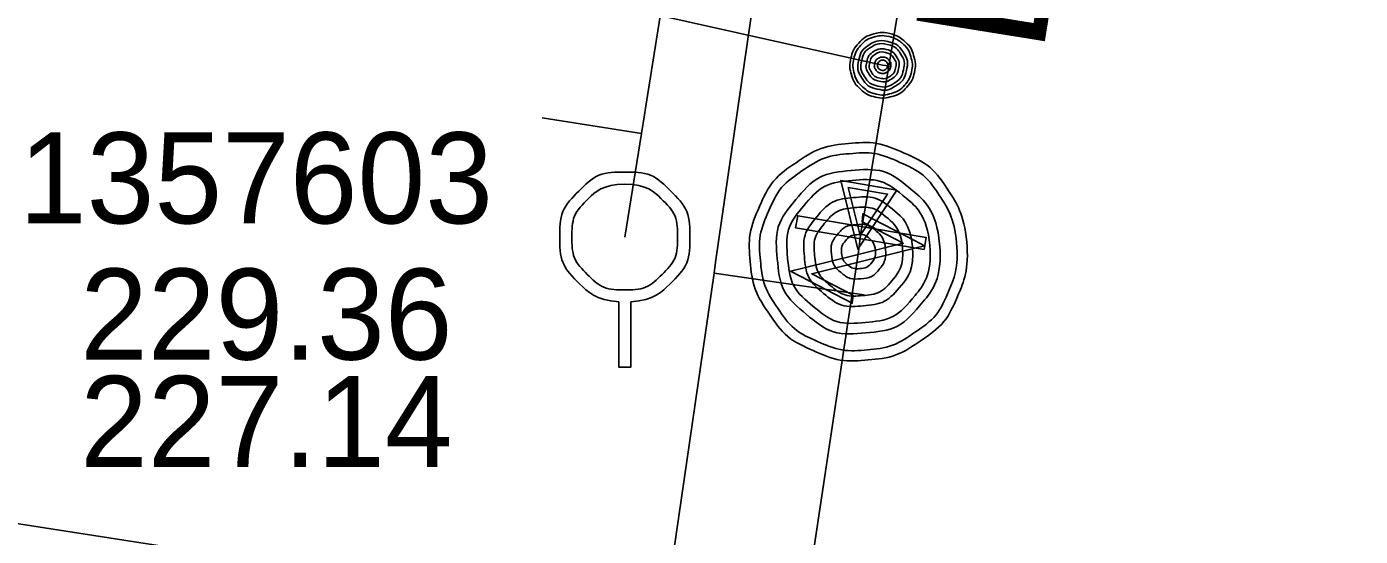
# Model space of a CAD drawing. Extents: x -595129 to -593591, y -1168385 to -1166898.
# Drawn here: x -594572.5 to -594551.99, y -1167292.77 to -1167284.93 of the extents above; entities that cross this region are included whole.
import ezdxf

# ---------------------------------------------------------------- set-up
doc = ezdxf.new("R2010")
doc.units = 0
for name, color, linetype in [('DA V Řad popis', 7, 'Continuous'), ('Default', 7, 'Continuous'), ('Identifikace', 7, 'Continuous'), ('Kanalizační přípojka', 7, 'Continuous'), ('Kanalizační stoka', 7, 'Continuous'), ('Kanalizační šachta', 7, 'Continuous'), ('Popis šachty', 7, 'Continuous'), ('V Lomový bod', 7, 'Continuous'), ('V Přípojka', 7, 'Continuous'), ('V Uzávěr', 7, 'Continuous'), ('V Řad', 7, 'Continuous')]:
    doc.layers.add(name, color=color, linetype=linetype)

msp = doc.modelspace()

# ---------------------------------------------------------------- linework, layer by layer
at = {"layer": 'Default'}
for points in [[(-594559.227, -1167285.037), (-594559.104, -1167285.065), (-594559.001, -1167285.154), (-594558.898, -1167285.243), (-594558.859, -1167285.375), (-594558.819, -1167285.507), (-594558.848, -1167285.635), (-594558.876, -1167285.762), (-594558.966, -1167285.864), (-594559.057, -1167285.966), (-594559.188, -1167286.004), (-594559.318, -1167286.042), (-594559.446, -1167286.014), (-594559.572, -1167285.986), (-594559.674, -1167285.895), (-594559.776, -1167285.805), (-594559.814, -1167285.674), (-594559.853, -1167285.544), (-594559.824, -1167285.417), (-594559.796, -1167285.289), (-594559.704, -1167285.186), (-594559.612, -1167285.083), (-594559.481, -1167285.046), (-594559.351, -1167285.009), (-594559.227, -1167285.037)], [(-594559.237, -1167285.083), (-594559.349, -1167285.058), (-594559.468, -1167285.091), (-594559.586, -1167285.124), (-594559.669, -1167285.218), (-594559.753, -1167285.311), (-594559.779, -1167285.427), (-594559.804, -1167285.542), (-594559.77, -1167285.66), (-594559.735, -1167285.778), (-594559.642, -1167285.86), (-594559.55, -1167285.942), (-594559.435, -1167285.968), (-594559.32, -1167285.994), (-594559.201, -1167285.959), (-594559.083, -1167285.924), (-594559.001, -1167285.832), (-594558.919, -1167285.74), (-594558.893, -1167285.625), (-594558.867, -1167285.509), (-594558.904, -1167285.389), (-594558.94, -1167285.269), (-594559.033, -1167285.188), (-594559.126, -1167285.108), (-594559.237, -1167285.083)], [(-594559.255, -1167285.159), (-594559.101, -1167285.193), (-594559.018, -1167285.325), (-594558.936, -1167285.456), (-594558.97, -1167285.608), (-594559.004, -1167285.76), (-594559.135, -1167285.843), (-594559.266, -1167285.926), (-594559.419, -1167285.892), (-594559.57, -1167285.858), (-594559.653, -1167285.727), (-594559.736, -1167285.596), (-594559.702, -1167285.444), (-594559.668, -1167285.292), (-594559.538, -1167285.208), (-594559.407, -1167285.125), (-594559.255, -1167285.159)], [(-594559.265, -1167285.204), (-594559.398, -1167285.174), (-594559.513, -1167285.247), (-594559.627, -1167285.32), (-594559.657, -1167285.453), (-594559.687, -1167285.586), (-594559.614, -1167285.7), (-594559.542, -1167285.815), (-594559.408, -1167285.845), (-594559.275, -1167285.875), (-594559.161, -1167285.802), (-594559.046, -1167285.729), (-594559.016, -1167285.596), (-594558.986, -1167285.463), (-594559.059, -1167285.348), (-594559.131, -1167285.234), (-594559.265, -1167285.204)], [(-594559.282, -1167285.281), (-594559.179, -1167285.304), (-594559.124, -1167285.392), (-594559.069, -1167285.479), (-594559.092, -1167285.581), (-594559.114, -1167285.682), (-594559.202, -1167285.737), (-594559.289, -1167285.792), (-594559.391, -1167285.77), (-594559.492, -1167285.747), (-594559.547, -1167285.66), (-594559.603, -1167285.572), (-594559.58, -1167285.471), (-594559.557, -1167285.37), (-594559.471, -1167285.314), (-594559.384, -1167285.258), (-594559.282, -1167285.281)], [(-594559.292, -1167285.327), (-594559.374, -1167285.308), (-594559.445, -1167285.353), (-594559.516, -1167285.398), (-594559.535, -1167285.481), (-594559.553, -1167285.563), (-594559.508, -1167285.634), (-594559.463, -1167285.705), (-594559.381, -1167285.723), (-594559.299, -1167285.742), (-594559.227, -1167285.697), (-594559.156, -1167285.652), (-594559.138, -1167285.569), (-594559.119, -1167285.487), (-594559.164, -1167285.416), (-594559.209, -1167285.345), (-594559.292, -1167285.327)], [(-594559.309, -1167285.403), (-594559.258, -1167285.415), (-594559.23, -1167285.459), (-594559.202, -1167285.502), (-594559.214, -1167285.553), (-594559.225, -1167285.603), (-594559.269, -1167285.631), (-594559.313, -1167285.659), (-594559.364, -1167285.648), (-594559.414, -1167285.636), (-594559.442, -1167285.593), (-594559.469, -1167285.549), (-594559.458, -1167285.498), (-594559.447, -1167285.448), (-594559.403, -1167285.42), (-594559.36, -1167285.392), (-594559.309, -1167285.403)], [(-594559.319, -1167285.449), (-594559.351, -1167285.442), (-594559.378, -1167285.459), (-594559.405, -1167285.476), (-594559.413, -1167285.508), (-594559.42, -1167285.54), (-594559.402, -1167285.567), (-594559.385, -1167285.595), (-594559.353, -1167285.602), (-594559.321, -1167285.609), (-594559.294, -1167285.591), (-594559.267, -1167285.574), (-594559.26, -1167285.542), (-594559.253, -1167285.51), (-594559.27, -1167285.483), (-594559.287, -1167285.456), (-594559.319, -1167285.449)], [(-594558.042, -1167288.241), (-594558.004, -1167288.661), (-594558.183, -1167289.079), (-594558.361, -1167289.496), (-594558.741, -1167289.758), (-594559.122, -1167290.02), (-594559.557, -1167290.059), (-594559.99, -1167290.098), (-594560.406, -1167289.915), (-594560.821, -1167289.731), (-594561.077, -1167289.355), (-594561.332, -1167288.978), (-594561.372, -1167288.544), (-594561.411, -1167288.113), (-594561.228, -1167287.696), (-594561.044, -1167287.28), (-594560.668, -1167287.024), (-594560.292, -1167286.769), (-594559.86, -1167286.73), (-594559.424, -1167286.69), (-594559.003, -1167286.877), (-594558.582, -1167287.064), (-594558.331, -1167287.442), (-594558.081, -1167287.82), (-594558.042, -1167288.241)], [(-594558.198, -1167288.255), (-594558.233, -1167287.875), (-594558.46, -1167287.532), (-594558.687, -1167287.189), (-594559.069, -1167287.019), (-594559.451, -1167286.85), (-594559.846, -1167286.886), (-594560.237, -1167286.921), (-594560.578, -1167287.152), (-594560.918, -1167287.383), (-594561.085, -1167287.761), (-594561.251, -1167288.139), (-594561.216, -1167288.53), (-594561.18, -1167288.923), (-594560.948, -1167289.265), (-594560.716, -1167289.607), (-594560.34, -1167289.773), (-594559.963, -1167289.939), (-594559.571, -1167289.903), (-594559.176, -1167289.867), (-594558.832, -1167289.629), (-594558.487, -1167289.391), (-594558.325, -1167289.014), (-594558.164, -1167288.636), (-594558.198, -1167288.255)], [(-594563.394, -1167289.166), (-594563.747, -1167289.137), (-594564.007, -1167288.877), (-594564.3, -1167288.586), (-594564.3, -1167288.172), (-594564.3, -1167287.756), (-594564.01, -1167287.463), (-594563.72, -1167287.17), (-594563.302, -1167287.17), (-594562.882, -1167287.17), (-594562.591, -1167287.463), (-594562.3, -1167287.756), (-594562.3, -1167288.172), (-594562.3, -1167288.586), (-594562.593, -1167288.877), (-594562.851, -1167289.137), (-594563.206, -1167289.166)], [(-594558.459, -1167288.277), (-594558.411, -1167288.803), (-594558.744, -1167289.199), (-594559.077, -1167289.596), (-594559.595, -1167289.643), (-594560.112, -1167289.69), (-594560.51, -1167289.357), (-594560.909, -1167289.025), (-594560.956, -1167288.504), (-594561.003, -1167287.991), (-594560.671, -1167287.592), (-594560.339, -1167287.193), (-594559.822, -1167287.146), (-594559.303, -1167287.099), (-594558.905, -1167287.428), (-594558.506, -1167287.757), (-594558.459, -1167288.277)], [(-594563.302, -1167287.356), (-594563.64, -1167287.356), (-594563.877, -1167287.593), (-594564.114, -1167287.83), (-594564.114, -1167288.168), (-594564.114, -1167288.506), (-594563.877, -1167288.743), (-594563.64, -1167288.981), (-594563.302, -1167288.981), (-594562.964, -1167288.981), (-594562.727, -1167288.743), (-594562.489, -1167288.506), (-594562.489, -1167288.168), (-594562.489, -1167287.83), (-594562.726, -1167287.593), (-594562.962, -1167287.356), (-594563.302, -1167287.356)], [(-594558.611, -1167288.291), (-594558.653, -1167287.836), (-594559.001, -1167287.547), (-594559.35, -1167287.257), (-594559.803, -1167287.298), (-594560.257, -1167287.339), (-594560.547, -1167287.687), (-594560.838, -1167288.035), (-594560.797, -1167288.49), (-594560.755, -1167288.944), (-594560.407, -1167289.234), (-594560.058, -1167289.524), (-594559.605, -1167289.483), (-594559.151, -1167289.442), (-594558.861, -1167289.095), (-594558.57, -1167288.748), (-594558.611, -1167288.291)], [(-594558.875, -1167288.317), (-594558.843, -1167288.666), (-594559.065, -1167288.931), (-594559.287, -1167289.195), (-594559.633, -1167289.227), (-594559.978, -1167289.258), (-594560.243, -1167289.036), (-594560.508, -1167288.814), (-594560.539, -1167288.468), (-594560.571, -1167288.125), (-594560.35, -1167287.859), (-594560.129, -1167287.593), (-594559.784, -1167287.562), (-594559.438, -1167287.53), (-594559.172, -1167287.75), (-594558.906, -1167287.969), (-594558.875, -1167288.317)], [(-594559.029, -1167288.331), (-594559.055, -1167288.05), (-594559.27, -1167287.87), (-594559.486, -1167287.691), (-594559.767, -1167287.716), (-594560.048, -1167287.742), (-594560.228, -1167287.957), (-594560.407, -1167288.173), (-594560.382, -1167288.454), (-594560.356, -1167288.734), (-594560.141, -1167288.914), (-594559.925, -1167289.094), (-594559.644, -1167289.069), (-594559.363, -1167289.043), (-594559.183, -1167288.828), (-594559.004, -1167288.612), (-594559.029, -1167288.331)], [(-594559.291, -1167288.355), (-594559.275, -1167288.53), (-594559.386, -1167288.663), (-594559.497, -1167288.795), (-594559.669, -1167288.81), (-594559.841, -1167288.826), (-594559.974, -1167288.715), (-594560.107, -1167288.604), (-594560.123, -1167288.43), (-594560.139, -1167288.26), (-594560.028, -1167288.127), (-594559.917, -1167287.994), (-594559.745, -1167287.978), (-594559.572, -1167287.962), (-594559.439, -1167288.072), (-594559.307, -1167288.182), (-594559.291, -1167288.355)], [(-594559.447, -1167288.369), (-594559.457, -1167288.262), (-594559.538, -1167288.192), (-594559.62, -1167288.122), (-594559.731, -1167288.132), (-594559.838, -1167288.142), (-594559.907, -1167288.226), (-594559.977, -1167288.309), (-594559.967, -1167288.416), (-594559.957, -1167288.527), (-594559.874, -1167288.595), (-594559.791, -1167288.662), (-594559.683, -1167288.653), (-594559.573, -1167288.643), (-594559.505, -1167288.561), (-594559.437, -1167288.479), (-594559.447, -1167288.369)]]:
    msp.add_open_spline(points, degree=3, dxfattribs=at)
at = {"layer": 'Kanalizační přípojka'}
for points in [[(-594564.573, -1167286.332), (-594563.045, -1167286.575)], [(-594559.622, -1167289.056), (-594561.928, -1167288.722)]]:
    msp.add_lwpolyline(points, dxfattribs=at)
at = {"layer": 'Kanalizační stoka'}
for points in [[(-594558.52, -1167265.18), (-594561.904, -1167288.556), (-594561.928, -1167288.722), (-594562.68, -1167293.91), (-594562.756, -1167294.117)], [(-594563.3, -1167288.17), (-594563.045, -1167286.575), (-594562.999, -1167286.288), (-594562.983, -1167286.185), (-594561.976, -1167279.88), (-594561.946, -1167279.695), (-594561.931, -1167279.599), (-594561.896, -1167279.377), (-594561.874, -1167279.242), (-594561.838, -1167279.016), (-594560.227, -1167268.924), (-594560.225, -1167268.909), (-594560.202, -1167268.766), (-594559.84, -1167266.5)], [(-594562.756, -1167294.117), (-594562.993, -1167294.076), (-594609.85, -1167286.79)]]:
    msp.add_lwpolyline(points, dxfattribs=at)
at = {"layer": 'Kanalizační šachta'}
msp.add_lwpolyline([(-594563.206, -1167289.166), (-594563.206, -1167290.17), (-594563.394, -1167290.17), (-594563.394, -1167289.166)], dxfattribs=at)
at = {"layer": 'V Lomový bod'}
for points in [[(-594559.116, -1167287.445), (-594559.715, -1167288.357), (-594559.981, -1167287.299), (-594559.116, -1167287.445)], [(-594559.865, -1167287.406), (-594559.679, -1167288.146), (-594559.261, -1167287.508), (-594559.865, -1167287.406)], [(-594560.581, -1167288.651), (-594559.714, -1167288.436), (-594559.018, -1167288.265), (-594559.653, -1167287.933), (-594559.638, -1167287.809), (-594558.847, -1167288.223), (-594558.693, -1167288.304), (-594558.862, -1167288.346), (-594559.728, -1167288.56), (-594560.425, -1167288.733), (-594559.789, -1167289.064), (-594559.804, -1167289.188), (-594560.596, -1167288.774), (-594560.751, -1167288.694), (-594560.581, -1167288.651)], [(-594558.693, -1167288.304), (-594558.691, -1167288.303), (-594558.692, -1167288.304), (-594558.693, -1167288.304)], [(-594560.752, -1167288.693), (-594560.751, -1167288.692), (-594560.751, -1167288.694), (-594560.752, -1167288.693)]]:
    msp.add_lwpolyline(points, dxfattribs=at)
at = {"layer": 'V Přípojka'}
msp.add_lwpolyline([(-594559.239, -1167285.536), (-594559.336, -1167285.526), (-594565.983, -1167284.039)], dxfattribs=at)
at = {"layer": 'V Uzávěr'}
msp.add_lwpolyline([(-594560.674, -1167288.026), (-594560.642, -1167287.841), (-594558.668, -1167288.173), (-594558.699, -1167288.359), (-594560.674, -1167288.026)], dxfattribs=at)
at = {"layer": 'V Řad'}
for points in [[(-594551.99, -1167240.77), (-594552.69, -1167245.105), (-594553.554, -1167250.422), (-594554.883, -1167258.738), (-594555.411, -1167261.981), (-594555.767, -1167264.162), (-594557.143, -1167272.706), (-594557.983, -1167277.938), (-594558.357, -1167280.202), (-594558.56, -1167281.49), (-594559.239, -1167285.536), (-594559.596, -1167287.667)], [(-594559.596, -1167287.667), (-594559.67, -1167288.1)], [(-594559.67, -1167288.1), (-594559.709, -1167288.394), (-594559.721, -1167288.497)], [(-594559.721, -1167288.497), (-594560.82, -1167295.8)]]:
    msp.add_lwpolyline(points, dxfattribs=at)

# ---------------------------------------------------------------- texts
at = {"layer": 'DA V Řad popis'}
msp.add_text('DN 100 LT', height=2, rotation=80.8443, dxfattribs=at).set_placement((-594556.876, -1167285.373))
at = {"layer": 'Identifikace'}
msp.add_text('1357603', height=1.4, dxfattribs=at).set_placement((-594572.617, -1167287.958))
at = {"layer": 'Popis šachty'}
for s, p in [('229.36', (-594571.676, -1167290.054)), ('227.14', (-594571.676, -1167291.704))]:
    msp.add_text(s, height=1.4, dxfattribs=at).set_placement(p)

doc.saveas('drawing.dxf')
